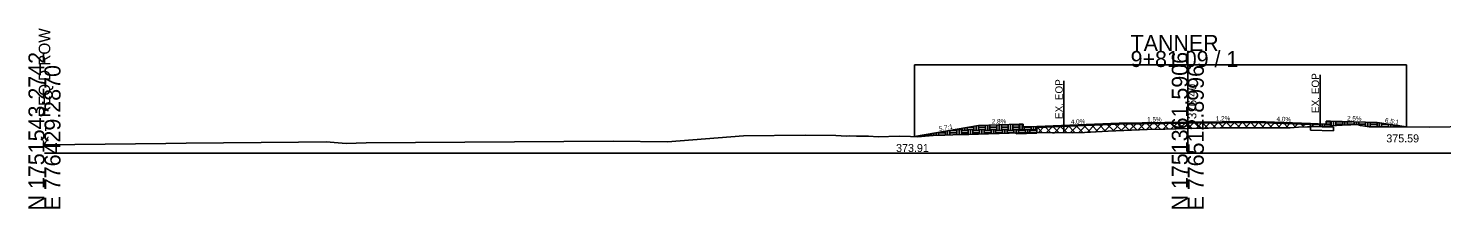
# Model space of a CAD drawing. Extents: x 774192 to 776597, y 1750236 to 1752784.
# Drawn here: x 774680.5 to 774927.8, y 1752748.9 to 1752780.4 of the extents above; entities that cross this region are included whole.
import ezdxf

# ---------------------------------------------------------------- set-up
doc = ezdxf.new("R2010")
doc.units = 0
for name, color, linetype in [('ControlPoints', 7, 'Continuous'), ('Default', 7, 'Continuous'), ('Observations', 7, 'Continuous'), ('Setups', 7, 'Continuous'), ('SHEET_BORDER_TX', 7, 'Continuous'), ('SHEET_DATE_DGN_TX', 7, 'Continuous'), ('SHEET_LOGO', 7, 'Continuous'), ('SHEET_PLOTTING_SHAPE', 7, 'Continuous'), ('SHEET_PRELIM', 7, 'Continuous'), ('SHEET_PROJ_NUMBER', 7, 'Continuous'), ('SHEET_TITLE_BLOCK_TX', 7, 'Continuous'), ('SHEET_WORK_NUMBER', 7, 'Continuous'), ('TS_BACKBONE', 7, 'Continuous'), ('TS_DIMENSIONS', 7, 'Continuous')]:
    doc.layers.add(name, color=color, linetype=linetype)

msp = doc.modelspace()

# ---------------------------------------------------------------- linework, layer by layer
at = {"layer": 'ControlPoints'}
msp.add_lwpolyline([(774683.33, 1752760.05), (774704.57, 1752760.25), (774708.11, 1752760.3), (774727.79, 1752760.49), (774732.6, 1752760.55), (774736.13, 1752760.25), (774739.58, 1752760.39), (774782.8, 1752760.66), (774792.32, 1752760.56), (774805.6, 1752761.63), (774816.37, 1752761.75), (774821.78, 1752761.67), (774823.64, 1752761.56), (774824.17, 1752761.58), (774825.35, 1752761.57), (774826.93, 1752761.54), (774827.49, 1752761.52), (774829.14, 1752761.45), (774832.84, 1752761.56), (774834.81, 1752761.51), (774836.05, 1752761.46), (774838.8, 1752761.67), (774843.93, 1752761.81), (774845.04, 1752761.82), (774848.47, 1752761.95), (774850.36, 1752762.01), (774853.81, 1752762.12), (774855.87, 1752762.14), (774858.73, 1752762.16), (774859.64, 1752762.14), (774859.99, 1752762.14), (774861.66, 1752762.2), (774863.25, 1752762.15), (774865.24, 1752762.19), (774869.4, 1752762.41), (774876.24, 1752762.73), (774879.31, 1752762.78), (774883.33, 1752762.88), (774886.97, 1752762.96), (774888.98, 1752763), (774889.55, 1752763), (774891.79, 1752763), (774892.51, 1752762.99), (774893.63, 1752763.02), (774901.23, 1752763.03), (774902.69, 1752763.12), (774905.82, 1752763.24), (774906.49, 1752763.25), (774910.36, 1752763.47), (774911.87, 1752763.54), (774912.5, 1752763.57), (774912.99, 1752763.59), (774913.55, 1752763.41), (774915.08, 1752763.2), (774918.23, 1752763.18), (774925.61, 1752763.13), (774932.81, 1752763.22)], dxfattribs=at)
at = {"layer": 'Default'}
for p, q in [((774871.34, 1752763.63), (774856.91, 1752763.05)), ((774871.34, 1752763.63), (774883.34, 1752763.81)), ((774883.34, 1752763.81), (774895.34, 1752763.95)), ((774895.33, 1752763.95), (774904.79, 1752763.57))]:
    msp.add_line(p, q, dxfattribs=at)
at = {"layer": 'Setups'}
for p, q in [((774883.33, 1752758.57), (774883.33, 1752776.43)), ((774683.33, 1752758.57), (774883.33, 1752758.57)), ((774883.33, 1752758.57), (775083.33, 1752758.57))]:
    msp.add_line(p, q, dxfattribs=at)
at = {"layer": 'SHEET_BORDER_TX'}
for p, q in [((774853.32, 1752761.95), (774853.32, 1752762.62)), ((774856.93, 1752762.05), (774853.32, 1752761.95)), ((774904.78, 1752762.57), (774908.82, 1752762.47)), ((774908.82, 1752762.47), (774908.82, 1752763.14))]:
    msp.add_line(p, q, dxfattribs=at)
for points in [[(774853.32, 1752762.62), (774856.91, 1752762.72), (774856.93, 1752762.05)], [(774904.78, 1752762.57), (774904.79, 1752763.24), (774908.82, 1752763.14)]]:
    msp.add_lwpolyline(points, dxfattribs=at)
at = {"layer": 'SHEET_LOGO'}
for p, q in [((774861.65, 1752771.2), (774861.65, 1752762.2)), ((774906.5, 1752772.25), (774906.5, 1752763.25)), ((774906.5, 1752772.25), (774906.5, 1752763.25))]:
    msp.add_line(p, q, dxfattribs=at)
at = {"layer": 'SHEET_PLOTTING_SHAPE'}
for p, q in [((774853.82, 1752762.63), (774853.82, 1752763.63)), ((774904.79, 1752763.74), (774904.79, 1752763.24)), ((774908.32, 1752763.15), (774908.32, 1752764.15)), ((774856.91, 1752762.72), (774853.82, 1752762.63)), ((774856.91, 1752763.22), (774856.91, 1752762.72)), ((774904.79, 1752763.24), (774908.32, 1752763.15))]:
    msp.add_line(p, q, dxfattribs=at)
at = {"layer": 'SHEET_PROJ_NUMBER'}
for p, q in [((774835.55, 1752761.48), (774835.55, 1752773.98)), ((774835.55, 1752773.98), (774921.57, 1752773.98)), ((774921.57, 1752773.98), (774921.57, 1752763.16))]:
    msp.add_line(p, q, dxfattribs=at)
at = {"layer": 'SHEET_TITLE_BLOCK_TX'}
for p, q in [((774853.82, 1752763.63), (774846.7, 1752763.43)), ((774854.53, 1752763.65), (774853.82, 1752763.63)), ((774854.53, 1752763.15), (774854.53, 1752763.65)), ((774871.33, 1752763.8), (774856.91, 1752763.22)), ((774871.33, 1752763.8), (774883.33, 1752763.98)), ((774883.33, 1752763.98), (774895.33, 1752764.11)), ((774895.33, 1752764.11), (774904.79, 1752763.74)), ((774904.79, 1752763.74), (774907.51, 1752763.67)), ((774907.51, 1752763.67), (774907.51, 1752764.17)), ((774907.51, 1752764.17), (774908.32, 1752764.15)), ((774908.32, 1752764.15), (774916.45, 1752763.95)), ((774916.45, 1752763.95), (774921.57, 1752763.16)), ((774846.7, 1752763.43), (774835.55, 1752761.48)), ((774856.91, 1752763.22), (774854.53, 1752763.15))]:
    msp.add_line(p, q, dxfattribs=at)
at = {"layer": 'SHEET_WORK_NUMBER'}
for p, q in [((774856.91, 1752762.72), (774856.91, 1752762.15)), ((774904.79, 1752763.24), (774904.79, 1752763.2))]:
    msp.add_line(p, q, dxfattribs=at)
msp.add_lwpolyline([(774856.91, 1752762.15), (774858.73, 1752762.16), (774859.64, 1752762.14), (774859.99, 1752762.14), (774861.66, 1752762.2), (774863.25, 1752762.15), (774865.24, 1752762.19), (774869.4, 1752762.41), (774876.24, 1752762.73), (774879.31, 1752762.78), (774883.33, 1752762.88), (774886.97, 1752762.96), (774888.98, 1752763), (774889.55, 1752763), (774891.79, 1752763), (774892.51, 1752762.99), (774893.63, 1752763.02), (774901.23, 1752763.03), (774902.69, 1752763.12), (774904.79, 1752763.2)], dxfattribs=at)
at = {"layer": 'TS_BACKBONE'}
for p, q in [((774849.93, 1752763.53), (774849.93, 1752762.63)), ((774850.33, 1752763.54), (774850.33, 1752762.63)), ((774850.73, 1752763.55), (774850.73, 1752762.63)), ((774850.82, 1752763.54), (774851.82, 1752763.54)), ((774851.93, 1752763.58), (774851.93, 1752762.63)), ((774852.33, 1752763.59), (774852.33, 1752762.63)), ((774852.73, 1752763.6), (774852.73, 1752762.63)), ((774852.82, 1752763.54), (774853.82, 1752763.54)), ((774853.93, 1752763.63), (774853.93, 1752762.64)), ((774854.33, 1752763.63), (774854.33, 1752762.65)), ((774862.84, 1752762.17), (774864.18, 1752763.51)), ((774864.26, 1752762.17), (774865.66, 1752763.57)), ((774865.04, 1752763.55), (774866.34, 1752762.25)), ((774865.71, 1752762.21), (774867.13, 1752763.63)), ((774866.4, 1752763.6), (774867.68, 1752762.32)), ((774867.21, 1752762.29), (774868.6, 1752763.69)), ((774867.76, 1752763.66), (774869.02, 1752762.39)), ((774868.7, 1752762.37), (774870.08, 1752763.75)), ((774869.12, 1752763.71), (774870.37, 1752762.45)), ((774870.19, 1752762.44), (774871.54, 1752763.8)), ((774870.48, 1752763.76), (774871.72, 1752762.52)), ((774871.67, 1752762.51), (774872.98, 1752763.82)), ((774871.85, 1752763.81), (774873.07, 1752762.58)), ((774873.16, 1752762.59), (774874.41, 1752763.84)), ((774873.24, 1752763.83), (774874.42, 1752762.65)), ((774874.64, 1752762.66), (774875.85, 1752763.87)), ((774874.64, 1752763.85), (774875.77, 1752762.71)), ((774876.03, 1752763.87), (774877.15, 1752762.74)), ((774876.13, 1752762.73), (774877.29, 1752763.89)), ((774877.42, 1752763.89), (774878.55, 1752762.77)), ((774877.56, 1752762.75), (774878.72, 1752763.91)), ((774878.82, 1752763.91), (774879.93, 1752762.79)), ((774879, 1752762.77), (774880.16, 1752763.93)), ((774880.21, 1752763.93), (774881.31, 1752762.83)), ((774880.45, 1752762.8), (774881.59, 1752763.95)), ((774881.6, 1752763.95), (774882.69, 1752762.86)), ((774881.9, 1752762.84), (774883.03, 1752763.97)), ((774883, 1752763.97), (774884.07, 1752762.89)), ((774883.35, 1752762.88), (774884.46, 1752763.99)), ((774884.39, 1752763.99), (774885.45, 1752762.93)), ((774884.8, 1752762.91), (774885.89, 1752764.01)), ((774885.79, 1752764), (774886.84, 1752762.96)), ((774886.25, 1752762.95), (774887.32, 1752764.02)), ((774887.19, 1752764.02), (774888.22, 1752762.99)), ((774887.69, 1752762.98), (774888.75, 1752764.04)), ((774888.59, 1752764.04), (774889.63, 1752763)), ((774889.13, 1752763), (774890.18, 1752764.05)), ((774889.99, 1752764.05), (774891.04, 1752763)), ((774890.54, 1752763), (774891.61, 1752764.07)), ((774891.38, 1752764.07), (774892.47, 1752762.99)), ((774891.96, 1752763), (774893.04, 1752764.09)), ((774892.78, 1752764.09), (774893.84, 1752763.02)), ((774893.38, 1752763.01), (774894.47, 1752764.1)), ((774894.18, 1752764.1), (774895.26, 1752763.02)), ((774894.81, 1752763.02), (774895.88, 1752764.09)), ((774895.59, 1752764.1), (774896.67, 1752763.03)), ((774896.22, 1752763.03), (774897.24, 1752764.04)), ((774897.07, 1752764.05), (774898.08, 1752763.03)), ((774897.64, 1752763.03), (774898.6, 1752763.98)), ((774898.54, 1752763.99), (774899.5, 1752763.03)), ((774899.06, 1752763.03), (774899.96, 1752763.93)), ((774900.01, 1752763.93), (774900.91, 1752763.03)), ((774900.47, 1752763.03), (774901.32, 1752763.88)), ((774901.48, 1752763.87), (774902.26, 1752763.09)), ((774901.93, 1752763.07), (774902.68, 1752763.82)), ((774902.96, 1752763.81), (774903.61, 1752763.15)), ((774903.42, 1752763.15), (774904.04, 1752763.77)), ((774904.43, 1752763.75), (774904.79, 1752763.39)), ((774904.83, 1752763.74), (774904.83, 1752763.24)), ((774905.23, 1752763.73), (774905.23, 1752763.23)), ((774905.32, 1752763.66), (774906.32, 1752763.66)), ((774906.43, 1752763.7), (774906.43, 1752763.2)), ((774906.83, 1752763.69), (774906.83, 1752763.19)), ((774907.23, 1752763.68), (774907.23, 1752763.18)), ((774907.32, 1752763.66), (774908.32, 1752763.66)), ((774907.51, 1752764.06), (774908.32, 1752764.06)), ((774907.82, 1752764.16), (774907.82, 1752764.15)), ((774908.22, 1752764.15), (774908.22, 1752764.15)), ((774908.43, 1752764.15), (774908.43, 1752763.36)), ((774908.83, 1752764.14), (774908.83, 1752763.38)), ((774909.23, 1752764.13), (774909.23, 1752763.41)), ((774909.32, 1752764.06), (774910.32, 1752764.06)), ((774909.32, 1752763.66), (774910.32, 1752763.66)), ((774910.43, 1752764.1), (774910.43, 1752763.47)), ((774910.83, 1752764.09), (774910.83, 1752763.49)), ((774911.23, 1752764.08), (774911.23, 1752763.51)), ((774911.32, 1752764.06), (774912.1, 1752764.06)), ((774911.32, 1752763.66), (774912.32, 1752763.66)), ((774912.43, 1752764.05), (774912.43, 1752763.56)), ((774912.83, 1752764.04), (774912.83, 1752763.58)), ((774913.23, 1752764.03), (774913.23, 1752763.52)), ((774913.32, 1752763.66), (774914.32, 1752763.66)), ((774914.43, 1752764), (774914.43, 1752763.29)), ((774914.83, 1752763.99), (774914.83, 1752763.23)), ((774915.23, 1752763.98), (774915.23, 1752763.2)), ((774915.32, 1752763.66), (774916.32, 1752763.66)), ((774916.43, 1752763.95), (774916.43, 1752763.19)), ((774916.83, 1752763.89), (774916.83, 1752763.19)), ((774917.23, 1752763.83), (774917.23, 1752763.19)), ((774917.32, 1752763.66), (774918.32, 1752763.66)), ((774918.43, 1752763.65), (774918.43, 1752763.18)), ((774918.83, 1752763.58), (774918.83, 1752763.18)), ((774919.23, 1752763.52), (774919.23, 1752763.18)), ((774835.93, 1752761.54), (774835.93, 1752761.46)), ((774836.33, 1752761.61), (774836.33, 1752761.48)), ((774836.73, 1752761.64), (774836.73, 1752761.51)), ((774836.82, 1752761.55), (774837.25, 1752761.55)), ((774836.92, 1752761.72), (774836.92, 1752761.64)), ((774837.32, 1752761.79), (774837.32, 1752761.64)), ((774837.72, 1752761.86), (774837.72, 1752761.64)), ((774837.82, 1752761.74), (774838.82, 1752761.74)), ((774837.93, 1752761.64), (774837.93, 1752761.6)), ((774838.33, 1752761.64), (774838.33, 1752761.63)), ((774838.92, 1752762.07), (774838.92, 1752761.67)), ((774839.32, 1752762.14), (774839.32, 1752761.68)), ((774839.72, 1752762.21), (774839.72, 1752761.69)), ((774839.82, 1752762.14), (774840.82, 1752762.14)), ((774839.82, 1752761.74), (774840.82, 1752761.74)), ((774840.92, 1752762.42), (774840.92, 1752761.73)), ((774841.32, 1752762.49), (774841.32, 1752761.74)), ((774841.72, 1752762.56), (774841.72, 1752761.75)), ((774841.82, 1752762.54), (774842.82, 1752762.54)), ((774841.82, 1752762.14), (774842.82, 1752762.14)), ((774842.33, 1752762.67), (774842.33, 1752762.63)), ((774842.73, 1752762.74), (774842.73, 1752762.63)), ((774842.82, 1752762.74), (774843.82, 1752762.74)), ((774842.92, 1752762.64), (774842.92, 1752761.78)), ((774843.32, 1752762.64), (774843.32, 1752761.79)), ((774843.72, 1752762.64), (774843.72, 1752761.81)), ((774843.82, 1752762.54), (774844.82, 1752762.54)), ((774843.82, 1752762.14), (774844.82, 1752762.14)), ((774843.93, 1752762.95), (774843.93, 1752762.63)), ((774844.33, 1752763.02), (774844.33, 1752762.63)), ((774844.73, 1752763.09), (774844.73, 1752762.63)), ((774844.82, 1752762.74), (774845.82, 1752762.74)), ((774844.92, 1752762.64), (774844.92, 1752761.82)), ((774845.03, 1752763.14), (774845.82, 1752763.14)), ((774845.32, 1752762.64), (774845.32, 1752761.83)), ((774845.72, 1752762.64), (774845.72, 1752761.84)), ((774845.82, 1752762.54), (774846.82, 1752762.54)), ((774845.82, 1752762.14), (774846.82, 1752762.14)), ((774845.93, 1752763.3), (774845.93, 1752762.63)), ((774846.33, 1752763.37), (774846.33, 1752762.63)), ((774846.73, 1752763.44), (774846.73, 1752762.63)), ((774846.82, 1752763.14), (774847.82, 1752763.14)), ((774846.82, 1752762.74), (774847.82, 1752762.74)), ((774846.92, 1752762.64), (774846.92, 1752761.89)), ((774847.32, 1752762.64), (774847.32, 1752761.91)), ((774847.72, 1752762.64), (774847.72, 1752761.92)), ((774847.82, 1752762.54), (774848.82, 1752762.54)), ((774847.82, 1752762.14), (774848.82, 1752762.14)), ((774847.93, 1752763.47), (774847.93, 1752762.63)), ((774848.33, 1752763.48), (774848.33, 1752762.63)), ((774848.73, 1752763.49), (774848.73, 1752762.63)), ((774848.82, 1752763.14), (774849.82, 1752763.14)), ((774848.82, 1752762.74), (774849.82, 1752762.74)), ((774848.92, 1752762.64), (774848.92, 1752761.97)), ((774849.32, 1752762.64), (774849.32, 1752761.98)), ((774849.72, 1752762.64), (774849.72, 1752761.99)), ((774849.82, 1752762.54), (774850.82, 1752762.54)), ((774849.82, 1752762.14), (774850.82, 1752762.14)), ((774850.82, 1752763.14), (774851.82, 1752763.14)), ((774850.82, 1752762.74), (774851.82, 1752762.74)), ((774850.92, 1752762.64), (774850.92, 1752762.03)), ((774851.32, 1752762.64), (774851.32, 1752762.04)), ((774851.72, 1752762.64), (774851.72, 1752762.05)), ((774851.82, 1752762.54), (774852.82, 1752762.54)), ((774851.82, 1752762.14), (774852.82, 1752762.14)), ((774852.82, 1752763.14), (774853.82, 1752763.14)), ((774852.82, 1752762.74), (774853.82, 1752762.74)), ((774852.92, 1752762.64), (774852.92, 1752762.09)), ((774853.32, 1752762.64), (774853.32, 1752762.1)), ((774853.72, 1752762.64), (774853.72, 1752762.11)), ((774853.82, 1752762.54), (774854.82, 1752762.54)), ((774853.82, 1752762.14), (774854.82, 1752762.14)), ((774853.93, 1752762.64), (774853.93, 1752762.63)), ((774854.33, 1752762.65), (774854.33, 1752762.63)), ((774854.73, 1752763.16), (774854.73, 1752762.66)), ((774854.73, 1752762.66), (774854.73, 1752762.63)), ((774854.82, 1752763.14), (774855.82, 1752763.14)), ((774854.82, 1752762.74), (774855.82, 1752762.74)), ((774854.92, 1752762.64), (774854.92, 1752762.13)), ((774855.32, 1752762.64), (774855.32, 1752762.13)), ((774855.72, 1752762.64), (774855.72, 1752762.14)), ((774855.82, 1752762.54), (774856.82, 1752762.54)), ((774855.82, 1752762.14), (774855.92, 1752762.14)), ((774855.93, 1752763.19), (774855.93, 1752762.69)), ((774855.93, 1752762.69), (774855.93, 1752762.63)), ((774856.33, 1752763.21), (774856.33, 1752762.71)), ((774856.33, 1752762.71), (774856.33, 1752762.63)), ((774856.73, 1752763.22), (774856.73, 1752762.72)), ((774856.73, 1752762.72), (774856.73, 1752762.63)), ((774856.82, 1752763.14), (774856.91, 1752763.14)), ((774856.82, 1752762.74), (774856.91, 1752762.74)), ((774856.91, 1752763.19), (774857.94, 1752762.15)), ((774857.16, 1752762.15), (774858.29, 1752763.28)), ((774858.24, 1752763.27), (774859.37, 1752762.14)), ((774858.59, 1752762.16), (774859.76, 1752763.34)), ((774859.6, 1752763.33), (774860.76, 1752762.17)), ((774859.99, 1752762.14), (774861.24, 1752763.39)), ((774860.96, 1752763.38), (774862.16, 1752762.18)), ((774861.45, 1752762.19), (774862.71, 1752763.45)), ((774862.32, 1752763.44), (774863.6, 1752762.16)), ((774863.68, 1752763.49), (774864.99, 1752762.18)), ((774905.32, 1752763.26), (774906.32, 1752763.26)), ((774907.32, 1752763.26), (774908.32, 1752763.26)), ((774908.22, 1752763.16), (774908.22, 1752763.15)), ((774915.32, 1752763.26), (774916.32, 1752763.26)), ((774917.32, 1752763.26), (774918.32, 1752763.26)), ((774919.32, 1752763.26), (774920.32, 1752763.26)), ((774920.43, 1752763.34), (774920.43, 1752763.17)), ((774920.83, 1752763.28), (774920.83, 1752763.17)), ((774921.23, 1752763.21), (774921.23, 1752763.16))]:
    msp.add_line(p, q, dxfattribs=at)

# ---------------------------------------------------------------- texts
at = {"layer": 'Observations'}
for s, p in [('375.59', (774918.06, 1752760.46)), ('373.91', (774832.3, 1752758.78))]:
    msp.add_text(s, height=1.4, dxfattribs=at).set_placement(p)
at = {"layer": 'Setups'}
for s, p in [('TANNER', (774873.33, 1752776.43)), ('9+81.09 / 1', (774873.33, 1752773.63))]:
    msp.add_text(s, height=2.8, dxfattribs=at).set_placement(p)
for s, p in [('N 1751543.2742', (774683.33, 1752748.57)), ('N 1751361.5906', (774883.33, 1752748.57)), ('E 776429.2870', (774686.13, 1752748.57)), ('E 776512.8996', (774886.13, 1752748.57))]:
    msp.add_text(s, height=2.8, rotation=90, dxfattribs=at).set_placement(p)
at = {"layer": 'SHEET_DATE_DGN_TX'}
for s, rotation, p in [('5.7:1', 9.9568, (774839.86, 1752762.44)), ('2.8%', 1.6089, (774849.06, 1752763.7)), ('4.0%', 2.2906, (774862.89, 1752763.66)), ('1.5%', 0.8449, (774876.24, 1752764.07)), ('1.2%', 0.665, (774888.24, 1752764.23)), ('4.0%', 357.7094, (774898.85, 1752764.17)), ('2.5%', 358.5906, (774911.19, 1752764.28)), ('6.5:1', 351.2577, (774917.78, 1752763.95))]:
    msp.add_text(s, height=0.8, rotation=rotation, dxfattribs=at).set_placement(p)
at = {"layer": 'SHEET_LOGO'}
for p in [(774861.45, 1752764.54), (774906.3, 1752765.59)]:
    msp.add_text('EX. EOP', height=1.3, rotation=90, dxfattribs=at).set_placement(p)
at = {"layer": 'SHEET_PRELIM'}
msp.add_text(' 376.40', height=1.5, rotation=90, dxfattribs=at).set_placement((774884.83, 1752763.98))
at = {"layer": 'TS_DIMENSIONS'}
msp.add_text("< -- REQ'D ROW", height=2, rotation=90, dxfattribs=at).set_placement((774684.33, 1752760.05))

doc.saveas('drawing.dxf')
